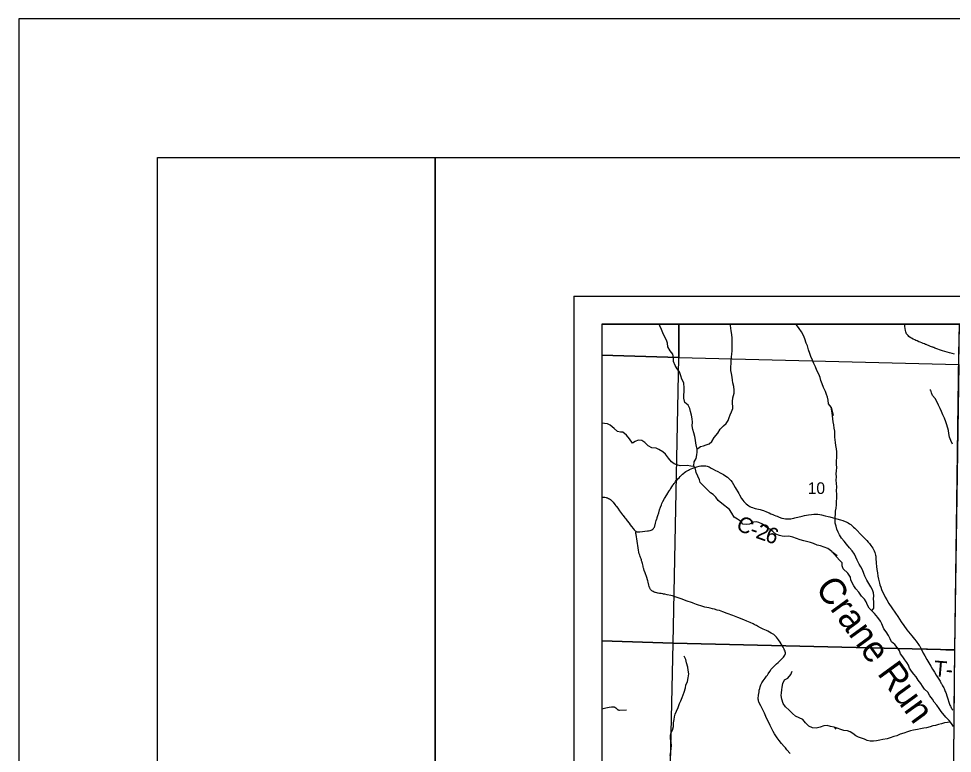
# Model space of a CAD drawing. Extents: x 0 to 34, y 0 to 22.
# Drawn here: x 0 to 3.363, y 19.354 to 22 of the extents above; entities that cross this region are included whole.
import ezdxf

# ---------------------------------------------------------------- set-up
doc = ezdxf.new("R2010")
doc.units = 0
for name, color, linetype in [('GM_X_Corporation', 7, 'Continuous'), ('GM_X_County_Road', 7, 'Continuous'), ('GM_X_County_Road_Text', 7, 'Continuous'), ('GM_X_Minor_River', 7, 'Continuous'), ('GM_X_Minor_River_Text', 7, 'Continuous'), ('GM_X_Section_Text', 7, 'Continuous'), ('GM_X_Township_Road', 7, 'Continuous'), ('GM_X_Township_Road_Text', 7, 'Continuous'), ('SH_Border', 7, 'Continuous'), ('SH_Cut_Line', 7, 'Continuous'), ('SH_Data', 7, 'Continuous')]:
    doc.layers.add(name, color=color, linetype=linetype)

msp = doc.modelspace()

# ---------------------------------------------------------------- linework, layer by layer
at = {"layer": 'GM_X_Corporation'}
for points in [[(8.9, 20.9), (2.1, 20.9), (2.1, 15.6606)], [(5.3543, 16.3597), (5.3699, 17.5116), (5.3717, 17.6123), (4.6401, 17.6298), (4.3705, 17.6391), (4.3669, 17.8198), (4.37, 17.9048), (4.3768, 18.4091), (4.3782, 18.6502), (4.377, 18.6713), (3.7035, 18.69), (3.3642, 18.7005), (3.3691, 19.5041), (3.3724, 19.7263), (3.3869, 20.7918), (3.3886, 20.9), (2.1, 20.9), (2.1, 15.6606)]]:
    msp.add_lwpolyline(points, dxfattribs=at)
for points in [[(2.378, 20.9), (2.1, 20.9), (2.1, 20.7886), (2.3781, 20.7796)], [(3.3885, 20.9), (2.378, 20.9), (2.3781, 20.7796), (3.3867, 20.754)], [(2.1, 20.7886), (2.1, 19.7588), (2.3578, 19.7506), (2.3781, 20.7796)], [(3.3867, 20.754), (3.3708, 19.7265), (2.3578, 19.7506), (2.3781, 20.7796)], [(2.1, 19.7588), (2.1, 18.7299), (2.3352, 18.7231), (2.3578, 19.7506)], [(3.3708, 19.7265), (3.3614, 18.7006), (2.3352, 18.7231), (2.3578, 19.7506)]]:
    msp.add_lwpolyline(points, close=True, dxfattribs=at)
at = {"layer": 'GM_X_County_Road'}
for points in [[(3.3712, 20.7922), (3.3627, 20.7936), (3.3531, 20.7959), (3.3442, 20.7984), (3.3359, 20.801), (3.3272, 20.8041), (3.3201, 20.8065), (3.3073, 20.811), (3.2997, 20.8138), (3.2963, 20.8151), (3.2945, 20.8158), (3.2928, 20.8164), (3.2882, 20.8182), (3.2841, 20.8198), (3.2773, 20.8226), (3.2733, 20.8242), (3.2715, 20.8249), (3.2687, 20.826), (3.2669, 20.8266), (3.2623, 20.8285), (3.2577, 20.8303), (3.2531, 20.8321), (3.2473, 20.8344), (3.2428, 20.8363), (3.2359, 20.8392), (3.2314, 20.8413), (3.228, 20.8429), (3.2219, 20.8459), (3.216, 20.8491), (3.2113, 20.8521), (3.2069, 20.8554), (3.2034, 20.8587), (3.2006, 20.8619), (3.1983, 20.8654), (3.1967, 20.8687), (3.1953, 20.8726), (3.1943, 20.8768), (3.1933, 20.8835), (3.1925, 20.8915), (3.1918, 20.9)], [(2.2237, 20.1532), (2.2244, 20.1528), (2.2264, 20.1523), (2.229, 20.1521), (2.2371, 20.1523), (2.2464, 20.1528), (2.2557, 20.1541), (2.2649, 20.1549), (2.2692, 20.1556), (2.2741, 20.1567), (2.2783, 20.1582), (2.2812, 20.1595), (2.2839, 20.1613), (2.2862, 20.1635), (2.2883, 20.1659), (2.2897, 20.1681), (2.2906, 20.1699), (2.2914, 20.1726), (2.2944, 20.1834), (2.2968, 20.1924), (2.298, 20.1959), (2.2983, 20.1965), (2.2987, 20.1983), (2.2998, 20.2012), (2.3002, 20.203), (2.3026, 20.2107), (2.3054, 20.2202), (2.3087, 20.2314), (2.3119, 20.2407), (2.3151, 20.2492), (2.317, 20.2537), (2.3205, 20.2608), (2.3263, 20.2715), (2.3341, 20.2846), (2.3432, 20.2991), (2.3442, 20.3007), (2.3452, 20.3022), (2.3471, 20.3053), (2.3491, 20.3083), (2.3526, 20.3139), (2.3545, 20.3169), (2.3554, 20.3182), (2.3566, 20.32), (2.3572, 20.3208), (2.3613, 20.3264), (2.362, 20.3273), (2.3633, 20.3291), (2.3647, 20.331), (2.3661, 20.3328), (2.3686, 20.3361), (2.3714, 20.3393), (2.3747, 20.3429), (2.3785, 20.3468), (2.3828, 20.3513), (2.3875, 20.3556), (2.3913, 20.3589), (2.3953, 20.3625), (2.3984, 20.3651), (2.4033, 20.3687), (2.4075, 20.3713), (2.4124, 20.3744), (2.4163, 20.3764), (2.4218, 20.3787), (2.4287, 20.3813), (2.4429, 20.3858), (2.451, 20.388), (2.4566, 20.3891), (2.459, 20.3894), (2.4639, 20.3897), (2.47, 20.3896), (2.4748, 20.389), (2.4801, 20.3877), (2.487, 20.3853), (2.4947, 20.3815), (2.5018, 20.3776), (2.51, 20.3731), (2.5155, 20.3703), (2.5288, 20.3635), (2.5386, 20.3581), (2.5475, 20.3526), (2.5529, 20.3486), (2.5557, 20.3462), (2.5605, 20.3415), (2.5649, 20.3363), (2.5694, 20.3305), (2.5746, 20.3228), (2.5813, 20.3116), (2.594, 20.2896), (2.5968, 20.2847), (2.6039, 20.2723), (2.6079, 20.2659), (2.6122, 20.2605), (2.6166, 20.256), (2.6203, 20.2526), (2.6247, 20.249), (2.6298, 20.2454), (2.6331, 20.2435), (2.6387, 20.2408), (2.6434, 20.239), (2.6488, 20.2373), (2.6524, 20.2363), (2.6646, 20.2337), (2.6712, 20.232), (2.6782, 20.2298), (2.6829, 20.2283), (2.6932, 20.2241), (2.7034, 20.2197), (2.7097, 20.217), (2.7161, 20.2145), (2.7212, 20.2122), (2.727, 20.2099), (2.7321, 20.2077), (2.7396, 20.2047), (2.7491, 20.2014), (2.7563, 20.1995), (2.7626, 20.1986), (2.7676, 20.1983), (2.7739, 20.1983), (2.7808, 20.1989), (2.7857, 20.1997), (2.7918, 20.2011), (2.7955, 20.2019), (2.8226, 20.2086), (2.831, 20.2107), (2.8377, 20.2119), (2.845, 20.2131), (2.8555, 20.2144), (2.8641, 20.2151), (2.8709, 20.2154), (2.8782, 20.2151), (2.8856, 20.2144), (2.8922, 20.2131), (2.9054, 20.2099), (2.9162, 20.2069), (2.9216, 20.2054), (2.9342, 20.2021), (2.9598, 20.1946), (2.9681, 20.192), (2.971, 20.191), (2.9808, 20.1872), (2.9875, 20.1841), (2.9927, 20.1809), (2.9972, 20.1777), (3.002, 20.1739), (3.0075, 20.1689), (3.0119, 20.1646), (3.0189, 20.1575), (3.0327, 20.1432), (3.0426, 20.1329), (3.0547, 20.1205), (3.0597, 20.115), (3.0645, 20.1093), (3.0695, 20.103), (3.0735, 20.0976), (3.0765, 20.093), (3.0796, 20.0877), (3.0816, 20.0832), (3.0838, 20.0775), (3.0852, 20.0728), (3.0863, 20.068), (3.0869, 20.0644), (3.0877, 20.057), (3.089, 20.0384), (3.09, 20.0267), (3.0913, 20.0155), (3.0929, 20.0044), (3.0952, 19.9915), (3.0973, 19.9818), (3.0996, 19.9721), (3.101, 19.9667), (3.1024, 19.9613), (3.105, 19.9523), (3.1077, 19.9446), (3.1114, 19.9361), (3.1171, 19.9243), (3.1215, 19.916), (3.1265, 19.9074), (3.1347, 19.8941), (3.1456, 19.8775), (3.1583, 19.8584), (3.1663, 19.8465), (3.1725, 19.8372), (3.1787, 19.8278), (3.1884, 19.8142), (3.1995, 19.799), (3.205, 19.7921), (3.211, 19.7844), (3.2169, 19.7773), (3.2269, 19.7655), (3.2328, 19.7583), (3.2354, 19.7549), (3.2389, 19.7498), (3.2439, 19.742), (3.2454, 19.7394), (3.2519, 19.7277)], [(2.1, 20.2773), (2.1022, 20.2772), (2.1077, 20.2766), (2.1117, 20.2761), (2.1156, 20.2754), (2.1182, 20.2747), (2.1208, 20.2738), (2.1242, 20.2724), (2.128, 20.2705), (2.132, 20.2678), (2.1357, 20.2647), (2.1383, 20.2621), (2.1415, 20.2584), (2.1475, 20.2505), (2.1508, 20.2459), (2.1533, 20.2424), (2.1576, 20.2364), (2.1642, 20.2273), (2.1717, 20.2174), (2.1747, 20.2135), (2.177, 20.2105), (2.1831, 20.2027), (2.1865, 20.1983), (2.1921, 20.1908), (2.1984, 20.1824), (2.2022, 20.1774), (2.2075, 20.1706), (2.2128, 20.1637), (2.2173, 20.1584), (2.22, 20.1557), (2.2226, 20.1537), (2.2237, 20.1532)], [(3.2519, 19.7277), (3.2582, 19.7153), (3.2639, 19.7046), (3.2706, 19.6921), (3.2778, 19.6798), (3.2852, 19.6676), (3.2921, 19.6566), (3.2985, 19.6462), (3.3052, 19.6352), (3.312, 19.6243), (3.3186, 19.6138), (3.3218, 19.6083), (3.3233, 19.6058), (3.3249, 19.6031), (3.3265, 19.6002), (3.3281, 19.5971), (3.3299, 19.5938), (3.3318, 19.5902), (3.3333, 19.587), (3.3349, 19.5836), (3.3363, 19.5802), (3.3377, 19.5767), (3.339, 19.5734), (3.3402, 19.5697), (3.3431, 19.5609), (3.3454, 19.5537), (3.3516, 19.5348), (3.353, 19.5305), (3.3543, 19.5271), (3.3558, 19.5241), (3.3574, 19.5209), (3.3591, 19.5178), (3.3608, 19.515), (3.3627, 19.5122), (3.3642, 19.5099)]]:
    msp.add_lwpolyline(points, dxfattribs=at)
at = {"layer": 'GM_X_Minor_River'}
for points in [[(2.9291, 20.0813), (2.9143, 20.0915), (2.9013, 20.0971), (2.8884, 20.1012), (2.8759, 20.1038), (2.8626, 20.1094), (2.8523, 20.1135), (2.8379, 20.1175), (2.8276, 20.1198), (2.8143, 20.1235), (2.8018, 20.1275), (2.7881, 20.1324), (2.7741, 20.1361), (2.7601, 20.1345), (2.7506, 20.1359), (2.7403, 20.1381), (2.727, 20.143), (2.7167, 20.1535), (2.706, 20.1611), (2.6965, 20.1663), (2.6866, 20.1731), (2.6771, 20.1806), (2.6661, 20.1855), (2.6566, 20.1873), (2.6471, 20.1861), (2.6327, 20.1788), (2.6218, 20.1776), (2.6081, 20.1798), (2.6004, 20.1903), (2.5894, 20.1979), (2.5768, 20.205), (2.5688, 20.2186), (2.56, 20.2322), (2.5325, 20.254), (2.5196, 20.2646), (2.5108, 20.2767), (2.5012, 20.2865), (2.4917, 20.2928), (2.4783, 20.3049), (2.4665, 20.3177), (2.4551, 20.3294), (2.452, 20.3393), (2.4469, 20.3521), (2.4408, 20.365), (2.4373, 20.3779), (2.4315, 20.39), (2.4333, 20.4033), (2.4401, 20.4162), (2.4426, 20.4288), (2.4441, 20.4387), (2.444, 20.4497), (2.442, 20.4595), (2.4393, 20.4717), (2.4377, 20.4815), (2.4357, 20.4955), (2.4318, 20.5084), (2.4283, 20.5206), (2.426, 20.5334), (2.4267, 20.5464), (2.4262, 20.5593), (2.4231, 20.5714), (2.4199, 20.585), (2.418, 20.596), (2.4118, 20.6081), (2.4, 20.6179), (2.3957, 20.6327), (2.3953, 20.6456), (2.3967, 20.6562), (2.397, 20.6691), (2.3953, 20.6889), (2.3884, 20.7013), (2.3849, 20.7135), (2.3803, 20.7275), (2.3719, 20.7384), (2.3642, 20.7513), (2.3584, 20.7649), (2.3587, 20.7786), (2.356, 20.7911), (2.3468, 20.8039), (2.3384, 20.8183), (2.3368, 20.8308), (2.3336, 20.8426), (2.3263, 20.855), (2.3206, 20.8679), (2.3152, 20.8804), (2.3094, 20.894), (2.3071, 20.9)], [(2.444, 20.4493), (2.4463, 20.4516), (2.4561, 20.4589), (2.4663, 20.4616), (2.4765, 20.4651), (2.4867, 20.4689), (2.4965, 20.4774), (2.5055, 20.4915), (2.5179, 20.5067), (2.5273, 20.5212), (2.5382, 20.5331), (2.548, 20.5422), (2.5555, 20.5533), (2.5592, 20.5632), (2.5622, 20.5735), (2.5671, 20.5834), (2.5719, 20.5959), (2.571, 20.6217), (2.5728, 20.6339), (2.5768, 20.6506), (2.5775, 20.662), (2.5759, 20.6757), (2.5728, 20.6882), (2.5716, 20.6976), (2.5704, 20.7094), (2.5672, 20.7223), (2.5653, 20.7325), (2.5656, 20.7458), (2.5666, 20.7584), (2.5669, 20.7682), (2.5676, 20.7819), (2.5687, 20.7914), (2.5697, 20.8032), (2.5704, 20.8165), (2.5702, 20.8495), (2.5689, 20.8624), (2.5669, 20.8757), (2.5654, 20.8851), (2.5645, 20.895), (2.564, 20.9)], [(2.9267, 20.6006), (2.9172, 20.6131), (2.9159, 20.6263), (2.9136, 20.6362), (2.9093, 20.6468), (2.9059, 20.657), (2.8993, 20.6714), (2.8939, 20.6846), (2.8897, 20.6968), (2.8866, 20.7077), (2.8823, 20.7195), (2.875, 20.7331), (2.8696, 20.746), (2.8642, 20.7577), (2.8592, 20.7698), (2.8534, 20.7827), (2.8492, 20.794), (2.8449, 20.8069), (2.841, 20.8213), (2.8368, 20.8312), (2.8318, 20.8463), (2.8268, 20.8592), (2.8202, 20.8724), (2.811, 20.8841), (2.8011, 20.8974), (2.7996, 20.9)], [(3.3014, 20.632), (3.2919, 20.6425), (3.288, 20.6523), (3.286, 20.6621), (3.2819, 20.6617)], [(3.3641, 20.4674), (3.3572, 20.481), (3.3529, 20.4927), (3.3509, 20.5056), (3.3493, 20.5169), (3.3435, 20.5369), (3.3396, 20.5479), (3.3342, 20.5607), (3.3292, 20.5728), (3.3245, 20.5849), (3.3191, 20.5962), (3.3126, 20.6082), (3.308, 20.6184), (3.3014, 20.632)], [(3.0736, 19.8667), (3.0804, 19.8772), (3.08, 19.8886), (3.0799, 19.9), (3.0786, 19.9105), (3.0797, 19.9215), (3.0796, 19.9318), (3.0757, 19.9423), (3.0696, 19.9533), (3.0623, 19.9657), (3.0546, 19.9774), (3.0481, 19.9921), (3.0438, 20.0022), (3.0395, 20.0143), (3.0338, 20.0256), (3.0276, 20.0354), (3.0203, 20.0494), (3.0153, 20.0607), (3.0103, 20.0712), (3.0023, 20.0829), (2.9931, 20.0945), (2.9816, 20.1077), (2.9729, 20.1186), (2.9637, 20.1295), (2.9564, 20.1408), (2.9518, 20.1509), (2.9472, 20.1615), (2.9444, 20.1717), (2.9413, 20.1834), (2.9412, 20.1929), (2.9415, 20.2046), (2.9425, 20.2152), (2.9424, 20.2259), (2.9442, 20.2369), (2.9453, 20.2494), (2.9455, 20.2611), (2.9473, 20.2733), (2.9472, 20.2869), (2.9463, 20.2994), (2.9466, 20.3142), (2.9457, 20.3259), (2.9445, 20.338), (2.9455, 20.3494), (2.945, 20.3608), (2.9453, 20.371), (2.9464, 20.3831), (2.9463, 20.3937), (2.9458, 20.407), (2.9464, 20.4195), (2.9467, 20.4301), (2.9466, 20.4403), (2.9458, 20.4509), (2.9438, 20.4627), (2.9418, 20.4732), (2.9406, 20.4831), (2.9397, 20.4929), (2.9396, 20.5035), (2.9392, 20.5141), (2.9376, 20.5247), (2.9359, 20.5368), (2.9343, 20.5474), (2.9327, 20.5584), (2.9315, 20.569), (2.9307, 20.58), (2.9267, 20.6006), (2.9341, 20.5724), (2.9338, 20.5705)], [(2.4323, 20.3883), (2.4304, 20.3873), (2.4209, 20.3884), (2.4084, 20.3902), (2.383, 20.39), (2.3708, 20.3926), (2.3613, 20.3971), (2.3514, 20.4043), (2.3403, 20.4171), (2.33, 20.4318), (2.3197, 20.4397), (2.306, 20.448), (2.2961, 20.4536), (2.2802, 20.4539), (2.2676, 20.4614), (2.2558, 20.4738), (2.2451, 20.4802), (2.2311, 20.482), (2.2205, 20.4766), (2.2107, 20.4713), (2.2, 20.4867), (2.1893, 20.5), (2.1767, 20.5113), (2.1672, 20.5112), (2.1573, 20.5134), (2.1447, 20.524), (2.1303, 20.5356), (2.1204, 20.5409), (2.1097, 20.5419), (2.1, 20.543)], [(3.0523, 19.8993), (3.0469, 19.9091), (3.0362, 19.9203), (3.0266, 19.9343), (3.0156, 19.9466), (3.0087, 19.9576), (3.0021, 19.9677), (2.9975, 19.9783), (2.9959, 19.9881), (2.9863, 20.0032), (2.97, 20.0185), (2.9665, 20.0287), (2.966, 20.0401), (2.9564, 20.0502), (2.9291, 20.0813), (2.9476, 20.0664), (2.9472, 20.066)], [(3.3673, 19.4502), (3.36, 19.4615), (3.352, 19.4724), (3.3398, 19.4848), (3.3222, 19.5051), (3.3153, 19.5156), (3.3073, 19.528), (3.2981, 19.5378), (3.2912, 19.5495), (3.2816, 19.5615), (3.2743, 19.5739), (3.2629, 19.5851), (3.2556, 19.5953), (3.2495, 19.6058), (3.2403, 19.6175), (3.233, 19.6295), (3.2243, 19.6393), (3.2162, 19.6502), (3.2093, 19.6611), (3.2047, 19.6713), (3.1989, 19.6811), (3.1921, 19.6909), (3.1848, 19.701), (3.1768, 19.7119), (3.1721, 19.7232), (3.1645, 19.7357), (3.1553, 19.7458), (3.1439, 19.7559), (3.1392, 19.7668), (3.1335, 19.7778), (3.1243, 19.7917), (3.1166, 19.8022), (3.1093, 19.8199), (3.1039, 19.8305), (3.0943, 19.8437), (3.0829, 19.8579), (3.0726, 19.8677), (3.063, 19.8767), (3.0577, 19.8872), (3.0523, 19.8993)], [(2.3461, 19.3456), (2.3487, 19.3589), (2.3501, 19.3714), (2.3515, 19.3824), (2.3507, 19.3946), (2.348, 19.4063), (2.3479, 19.4189), (2.3497, 19.4284), (2.3546, 19.4379), (2.359, 19.4508), (2.359, 19.4633), (2.3608, 19.4763), (2.3622, 19.4858), (2.3652, 19.4953), (2.3693, 19.5055), (2.3749, 19.5196), (2.3797, 19.5329), (2.3846, 19.5436), (2.3902, 19.5547), (2.3931, 19.5645), (2.3965, 19.5744), (2.4013, 19.5893), (2.4035, 19.5992), (2.4087, 19.6125), (2.4117, 19.6262), (2.4139, 19.6406), (2.4119, 19.6535), (2.4107, 19.6645), (2.4056, 19.6796), (2.4025, 19.6914), (2.3968, 19.7042)], [(2.9368, 19.4483), (2.9239, 19.4501), (2.9122, 19.4542), (2.8996, 19.4533), (2.8872, 19.4487), (2.8728, 19.4452), (2.8595, 19.4455), (2.8466, 19.4518), (2.8344, 19.4639), (2.8244, 19.476), (2.8107, 19.482), (2.7982, 19.4883), (2.7871, 19.4977), (2.7749, 19.5098), (2.7619, 19.5211), (2.7535, 19.5336), (2.7492, 19.5495), (2.7469, 19.562), (2.7476, 19.5719), (2.7483, 19.5821), (2.7497, 19.5924), (2.7523, 19.6053), (2.7583, 19.6182), (2.7707, 19.6248), (2.7809, 19.6374), (2.7857, 19.6499)], [(3.3569, 19.4658), (3.3452, 19.4655), (3.335, 19.4635), (3.3241, 19.4608), (3.3135, 19.4576), (3.3022, 19.4541), (3.2924, 19.4529), (3.2826, 19.4497), (3.2702, 19.4462), (3.2604, 19.4449), (3.2483, 19.4425), (3.2373, 19.4398), (3.223, 19.437), (3.2124, 19.4346), (3.2019, 19.4318), (3.1887, 19.4271), (3.1755, 19.4228), (3.1631, 19.4174), (3.1525, 19.415), (3.1393, 19.4096), (3.128, 19.4064), (3.1125, 19.4036), (3.102, 19.4008), (3.0903, 19.3988), (3.0789, 19.3972), (3.0672, 19.3975), (3.0566, 19.4), (3.0467, 19.4048), (3.0361, 19.4085), (3.0255, 19.4118), (3.0149, 19.4166), (3.005, 19.4252), (2.9951, 19.4316), (2.9856, 19.4349), (2.9724, 19.4366), (2.9368, 19.4483), (2.9432, 19.4409)]]:
    msp.add_lwpolyline(points, dxfattribs=at)
at = {"layer": 'GM_X_Township_Road'}
for points in [[(2.7788, 19.3537), (2.7674, 19.3668), (2.7616, 19.3733), (2.7567, 19.3789), (2.7479, 19.3893), (2.7394, 19.4001), (2.7321, 19.4101), (2.7276, 19.4168), (2.723, 19.4242), (2.7181, 19.4329), (2.7119, 19.445), (2.7074, 19.4539), (2.7022, 19.4645), (2.6976, 19.474), (2.6917, 19.487), (2.6865, 19.4982), (2.6837, 19.5038), (2.6794, 19.5127), (2.6727, 19.5254), (2.6686, 19.5337), (2.6663, 19.5395), (2.6653, 19.5424), (2.6645, 19.5454), (2.6641, 19.5491), (2.664, 19.5541), (2.6647, 19.5609), (2.6651, 19.564), (2.6667, 19.5757), (2.6678, 19.5818), (2.6692, 19.5878), (2.671, 19.5937), (2.6733, 19.6001), (2.6773, 19.6079), (2.6816, 19.6147), (2.6884, 19.6243), (2.6942, 19.6324), (2.6968, 19.6358), (2.6996, 19.6399), (2.702, 19.6435), (2.7063, 19.6503), (2.7097, 19.6554), (2.7133, 19.6597), (2.7175, 19.6643), (2.7196, 19.6666), (2.725, 19.6716), (2.7297, 19.6762), (2.7359, 19.6815), (2.7443, 19.6897), (2.7509, 19.6963), (2.7551, 19.7007), (2.7578, 19.7042), (2.7598, 19.7073), (2.7612, 19.7105), (2.7617, 19.7134), (2.7619, 19.7163), (2.7614, 19.7192), (2.7603, 19.7224), (2.7589, 19.7258), (2.7571, 19.7297), (2.7537, 19.7358), (2.7509, 19.7405), (2.7425, 19.7548), (2.7372, 19.7627), (2.7332, 19.7681), (2.7293, 19.7728), (2.7245, 19.7775), (2.7196, 19.7816), (2.7152, 19.7847), (2.711, 19.7872), (2.6984, 19.7937), (2.6932, 19.7961), (2.6815, 19.8015), (2.6725, 19.8063), (2.6618, 19.812), (2.6579, 19.814), (2.654, 19.8159), (2.649, 19.8183), (2.6456, 19.8198), (2.6344, 19.8249), (2.6231, 19.8298), (2.6203, 19.8311), (2.614, 19.8338), (2.6054, 19.8374), (2.5898, 19.8434), (2.5723, 19.8499), (2.5515, 19.858), (2.5358, 19.8639), (2.524, 19.8679), (2.5163, 19.8702), (2.5061, 19.8728), (2.4994, 19.8743), (2.4903, 19.8764), (2.4855, 19.8776), (2.4783, 19.8794), (2.4716, 19.881), (2.4573, 19.8852), (2.4491, 19.888), (2.4414, 19.8905), (2.4297, 19.8946), (2.4268, 19.8957), (2.4198, 19.8982), (2.4116, 19.9012), (2.4046, 19.9037), (2.3959, 19.907), (2.3866, 19.9104), (2.3714, 19.9158), (2.3608, 19.9192), (2.3554, 19.9208), (2.3495, 19.9223), (2.3361, 19.9251), (2.3276, 19.9267), (2.3227, 19.9276), (2.3203, 19.9281), (2.3148, 19.9291), (2.3081, 19.9302), (2.3039, 19.931), (2.3026, 19.9312), (2.2984, 19.932), (2.2942, 19.9332), (2.2924, 19.9337), (2.2889, 19.9349), (2.2855, 19.9365), (2.2834, 19.9377), (2.2808, 19.9395), (2.2782, 19.9421), (2.2763, 19.9441), (2.2748, 19.9466), (2.2738, 19.9487), (2.2733, 19.9498), (2.2728, 19.9509), (2.2714, 19.9543), (2.27, 19.9591), (2.2671, 19.9705), (2.266, 19.9753), (2.2609, 19.9906), (2.2575, 19.9999), (2.2561, 20.004), (2.2532, 20.0128), (2.2517, 20.0182), (2.251, 20.0206), (2.2497, 20.0254), (2.2491, 20.0277), (2.2476, 20.0331), (2.2466, 20.0373), (2.2457, 20.0409), (2.2454, 20.0421), (2.2439, 20.0474), (2.243, 20.0509), (2.2417, 20.055), (2.2409, 20.0573), (2.2403, 20.0591), (2.2389, 20.0632), (2.2372, 20.0678), (2.2355, 20.0731), (2.2341, 20.079), (2.2327, 20.0855), (2.2311, 20.0943), (2.2239, 20.142), (2.2235, 20.1459), (2.2233, 20.1488), (2.2234, 20.1505), (2.2236, 20.1521), (2.2237, 20.1532)], [(3.2519, 19.7277), (3.258, 19.7299), (3.2612, 19.7303), (3.2638, 19.7305), (3.2662, 19.7305), (3.273, 19.7304), (3.3028, 19.729), (3.339, 19.7273), (3.3529, 19.7268), (3.3591, 19.7268), (3.3655, 19.7264), (3.3726, 19.7258)], [(2.1, 19.514), (2.1154, 19.5174), (2.1275, 19.52), (2.1349, 19.5213), (2.1386, 19.5216), (2.1417, 19.5215), (2.1447, 19.521), (2.1476, 19.5198), (2.1506, 19.5176), (2.1545, 19.5137), (2.1565, 19.5122), (2.1587, 19.511), (2.1604, 19.5104), (2.1622, 19.51), (2.1641, 19.5099), (2.1891, 19.511)]]:
    msp.add_lwpolyline(points, dxfattribs=at)
at = {"layer": 'SH_Border'}
for points in [[(0.5, 21.5), (1.5, 21.5), (1.5, 0.5), (0.5, 0.5)], [(1.5, 21.5), (33.5, 21.5), (33.5, 0.5), (1.5, 0.5)]]:
    msp.add_lwpolyline(points, close=True, dxfattribs=at)
at = {"layer": 'SH_Cut_Line'}
msp.add_lwpolyline([(0, 0), (34, 0), (34, 22), (0, 22)], close=True, dxfattribs=at)
at = {"layer": 'SH_Data'}
for p, q in [((2, 21), (9, 21)), ((2, 21), (2, 14)), ((2.1, 20.9), (2.1, 14.1)), ((2.1, 20.9), (8.9, 20.9))]:
    msp.add_line(p, q, dxfattribs=at)

# ---------------------------------------------------------------- texts
at = {"layer": 'GM_X_County_Road_Text'}
for s, rotation, p in [('C', 332.8712, (2.5801, 20.1632)), ('2', 340.5258, (2.6518, 20.1309)), ('-', 341.1488, (2.6299, 20.1384)), ('6', 340.9002, (2.6852, 20.1191))]:
    msp.add_text(s, height=0.0568, rotation=rotation, dxfattribs=at).set_placement(p)
at = {"layer": 'GM_X_Minor_River_Text'}
msp.add_text('Crane Run', height=0.09469, rotation=306.0663, dxfattribs=at).set_placement((2.8666, 19.9487))
at = {"layer": 'GM_X_Section_Text'}
msp.add_text('10', height=0.04186, rotation=0, dxfattribs=at).set_placement((2.8422, 20.2882))
at = {"layer": 'GM_X_Township_Road_Text'}
for s, rotation, p in [('T', 355.0677, (3.2944, 19.632)), ('-', 356.6315, (3.3384, 19.6283))]:
    msp.add_text(s, height=0.0568, rotation=rotation, dxfattribs=at).set_placement(p)

doc.saveas('drawing.dxf')
